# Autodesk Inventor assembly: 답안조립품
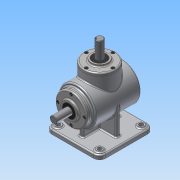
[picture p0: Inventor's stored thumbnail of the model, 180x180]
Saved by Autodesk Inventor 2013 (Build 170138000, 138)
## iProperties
Created: 2015-07
Part Number: 답안조립품
Document SubType Name: Assembly
Designer: Administrator
Author: Administrator
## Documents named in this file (14)
- C:\Users\Administrator\Desktop\450706V1005\답안조립품.iam
- C:\Users\Administrator\Desktop\450706V1005\본체.ipt
- C:\Users\Administrator\Desktop\450706V1005\M4.ipt
- C:\Users\Administrator\Desktop\450706V1005\메인 베벨기어.ipt
- C:\Users\Administrator\Desktop\450706V1005\메인 축.ipt
- 메인 축.ipt
- C:\Users\Administrator\Desktop\450706V1005\베어링 6203.ipt
- C:\Users\Administrator\Desktop\450706V1005\서브 베벨기어.ipt
- C:\Users\Administrator\Desktop\450706V1005\서브 축.ipt
- 서브 축.ipt
- C:\Users\Administrator\Desktop\450706V1005\오일실.ipt
- C:\Users\Administrator\Desktop\450706V1005\커버.ipt
- C:\Users\Administrator\Desktop\450706V1005\키 4x4.ipt
- C:\Users\Administrator\Desktop\450706V1005\키 5x5.ipt
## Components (8 placed, 1 different names)
1. M4:2 — 각도:1
2. M4:3
3. M4:4
4. M4:5
5. M4:1 — 각도:2
6. M4:6
7. M4:7
8. M4:8
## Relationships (2: Angle 2)
- 각도:1 [Angle]: M4:2
- 각도:2 [Angle]: M4:1
